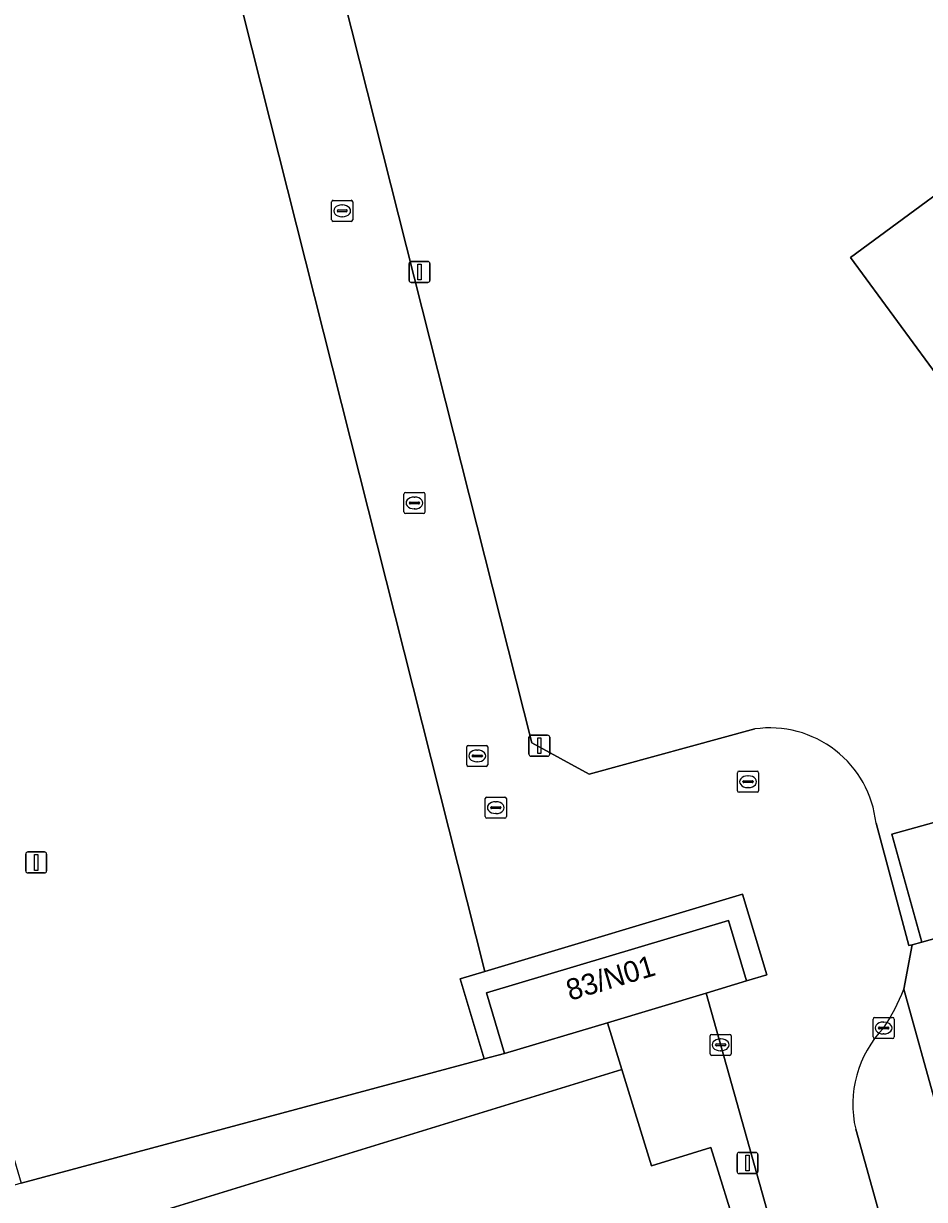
# Model space of a CAD drawing. Extents: x 161798 to 162385, y 382315 to 382833.
# Drawn here: x 161899.7 to 161942.5, y 382389.5 to 382445.3 of the extents above; entities that cross this region are included whole.
import ezdxf

# ---------------------------------------------------------------- set-up
doc = ezdxf.new("R2010")
doc.units = 0
for name, color, linetype in [('IMGEO_Erf', 7, 'Continuous'), ('IMGEO_Kolk', 7, 'Continuous'), ('IMGEO_Lichtmast', 7, 'Continuous'), ('IMGEO_Pand', 7, 'Continuous'), ('IMGEO_Pand_nummerreeks', 7, 'Continuous'), ('IMGEO_Parkeervlak_open', 7, 'Continuous'), ('IMGEO_Rijbaan_lokaal_open', 7, 'Continuous'), ('IMGEO_Rioolput', 7, 'Continuous'), ('IMGEO_Voetpad_open', 7, 'Continuous')]:
    doc.layers.add(name, color=color, linetype=linetype)

msp = doc.modelspace()

# ---------------------------------------------------------------- linework, layer by layer
at = {"layer": 'IMGEO_Erf'}
for points in [[(161943.046, 382494.363), (161935.085, 382489.806), (161935.055, 382489.789), (161936.244, 382487.804), (161938.108, 382484.585), (161938.514, 382483.884), (161935.731, 382482.274), (161935.489, 382482.679), (161932.899, 382481.486), (161935.813, 382475.159), (161932.857, 382473.767), (161932.015, 382475.589), (161928.142, 382473.799), (161924.693, 382472.205), (161925.53, 382470.395), (161922.269, 382468.888), (161918.832, 382467.419), (161919.424, 382465.747), (161910.817, 382462.697), (161923.855, 382411.141), (161926.575, 382409.655), (161934.439, 382411.796)], [(161944.197, 382427.091), (161938.983, 382434.18), (161953.966, 382445.201)], [(161940.197, 382407.325), (161941.76, 382401.512), (161941.909, 382401.548), (161942.37, 382401.676), (161940.944, 382406.8), (161949.609, 382409.212)]]:
    msp.add_lwpolyline(points, dxfattribs=at)
msp.add_arc((161935.153, 382406.772), 5.074, 6.2564, 98.086, dxfattribs=at)
at = {"layer": 'IMGEO_Kolk'}
for p, q in [((161914.341, 382435.967), (161914.341, 382436.819)), ((161914.416, 382436.893), (161915.268, 382436.893)), ((161915.342, 382436.819), (161915.342, 382435.967)), ((161914.6, 382436.387), (161914.6, 382436.399)), ((161915.038, 382436.35), (161914.64, 382436.35)), ((161914.643, 382436.436), (161915.041, 382436.436)), ((161914.829, 382436.673), (161914.854, 382436.673)), ((161915.084, 382436.399), (161915.084, 382436.387)), ((161915.268, 382435.893), (161914.416, 382435.893)), ((161914.852, 382436.113), (161914.827, 382436.113)), ((161917.773, 382422.099), (161917.773, 382422.951)), ((161917.848, 382423.025), (161918.7, 382423.025)), ((161918.261, 382422.805), (161918.286, 382422.805)), ((161918.774, 382422.951), (161918.774, 382422.099)), ((161918.032, 382422.519), (161918.032, 382422.531)), ((161918.47, 382422.482), (161918.072, 382422.482)), ((161918.075, 382422.568), (161918.473, 382422.568)), ((161918.284, 382422.245), (161918.259, 382422.245)), ((161918.516, 382422.531), (161918.516, 382422.519)), ((161918.7, 382422.025), (161917.848, 382422.025)), ((161920.755, 382410.091), (161920.755, 382410.943)), ((161920.83, 382411.017), (161921.682, 382411.017)), ((161921.014, 382410.511), (161921.014, 382410.523)), ((161921.057, 382410.56), (161921.455, 382410.56)), ((161921.243, 382410.797), (161921.268, 382410.797)), ((161921.498, 382410.523), (161921.498, 382410.511)), ((161921.756, 382410.943), (161921.756, 382410.091)), ((161921.682, 382410.017), (161920.83, 382410.017)), ((161921.452, 382410.474), (161921.054, 382410.474)), ((161921.266, 382410.237), (161921.241, 382410.237)), ((161933.616, 382408.865), (161933.616, 382409.717)), ((161933.691, 382409.791), (161934.543, 382409.791)), ((161934.104, 382409.571), (161934.129, 382409.571)), ((161934.617, 382409.717), (161934.617, 382408.865)), ((161933.875, 382409.285), (161933.875, 382409.297)), ((161934.313, 382409.248), (161933.915, 382409.248)), ((161933.918, 382409.334), (161934.316, 382409.334)), ((161934.127, 382409.011), (161934.102, 382409.011)), ((161934.359, 382409.297), (161934.359, 382409.285)), ((161934.543, 382408.791), (161933.691, 382408.791)), ((161940.056, 382397.172), (161940.056, 382398.024)), ((161940.131, 382398.098), (161940.983, 382398.098)), ((161940.544, 382397.878), (161940.569, 382397.878)), ((161941.057, 382398.024), (161941.057, 382397.172)), ((161932.316, 382396.372), (161932.316, 382397.224)), ((161932.391, 382397.298), (161933.243, 382397.298)), ((161933.317, 382397.224), (161933.317, 382396.372)), ((161940.983, 382397.098), (161940.131, 382397.098)), ((161940.315, 382397.592), (161940.315, 382397.604)), ((161940.753, 382397.555), (161940.355, 382397.555)), ((161940.358, 382397.641), (161940.756, 382397.641)), ((161940.567, 382397.318), (161940.542, 382397.318)), ((161940.799, 382397.604), (161940.799, 382397.592)), ((161932.575, 382396.792), (161932.575, 382396.804)), ((161933.013, 382396.755), (161932.615, 382396.755)), ((161932.618, 382396.841), (161933.016, 382396.841)), ((161932.804, 382397.078), (161932.829, 382397.078)), ((161933.059, 382396.804), (161933.059, 382396.792)), ((161933.243, 382396.298), (161932.391, 382396.298)), ((161932.827, 382396.518), (161932.802, 382396.518))]:
    msp.add_line(p, q, dxfattribs=at)
for points in [[(161914.341, 382435.967), (161914.341, 382436.819)], [(161914.416, 382436.893), (161915.268, 382436.893)], [(161915.342, 382436.819), (161915.342, 382435.967)], [(161915.268, 382435.893), (161914.416, 382435.893)], [(161917.773, 382422.099), (161917.773, 382422.951)], [(161917.848, 382423.025), (161918.7, 382423.025)], [(161918.774, 382422.951), (161918.774, 382422.099)], [(161918.7, 382422.025), (161917.848, 382422.025)], [(161920.755, 382410.091), (161920.755, 382410.943)], [(161920.83, 382411.017), (161921.682, 382411.017)], [(161921.756, 382410.943), (161921.756, 382410.091)], [(161921.682, 382410.017), (161920.83, 382410.017)], [(161933.616, 382408.865), (161933.616, 382409.717)], [(161933.691, 382409.791), (161934.543, 382409.791)], [(161934.617, 382409.717), (161934.617, 382408.865)], [(161934.543, 382408.791), (161933.691, 382408.791)], [(161940.056, 382397.172), (161940.056, 382398.024)], [(161940.131, 382398.098), (161940.983, 382398.098)], [(161941.057, 382398.024), (161941.057, 382397.172)], [(161932.316, 382396.372), (161932.316, 382397.224)], [(161932.391, 382397.298), (161933.243, 382397.298)], [(161933.317, 382397.224), (161933.317, 382396.372)], [(161940.983, 382397.098), (161940.131, 382397.098)], [(161933.243, 382396.298), (161932.391, 382396.298)]]:
    msp.add_lwpolyline(points, dxfattribs=at)
for centre, radius, start, end in [((161914.418, 382436.817), 0.0765, 91.552, 178.448), ((161914.418, 382436.817), 0.0765, 91.552, 178.448), ((161915.266, 382436.817), 0.0765, 1.552, 88.448), ((161915.266, 382436.817), 0.0765, 1.552, 88.448), ((161914.64, 382436.396), 0.0403, 85.8775, 175.7526), ((161914.637, 382436.386), 0.0366, 178.938, 274.7102), ((161915.041, 382436.393), 0.043, 264.8664, 352.4533), ((161915.045, 382436.398), 0.0386, 1.7309, 96.639), ((161914.418, 382435.969), 0.0765, 181.552, 268.448), ((161914.418, 382435.969), 0.0765, 181.552, 268.448), ((161915.266, 382435.969), 0.0765, 271.552, 358.448), ((161915.266, 382435.969), 0.0765, 271.552, 358.448), ((161917.85, 382422.949), 0.0765, 91.552, 178.448), ((161917.85, 382422.949), 0.0765, 91.552, 178.448), ((161918.698, 382422.949), 0.0765, 1.552, 88.448), ((161918.698, 382422.949), 0.0765, 1.552, 88.448), ((161918.072, 382422.528), 0.0403, 85.8775, 175.7526), ((161918.069, 382422.518), 0.0366, 178.938, 274.7102), ((161918.473, 382422.525), 0.043, 264.8664, 352.4533), ((161918.477, 382422.53), 0.0386, 1.7309, 96.639), ((161917.85, 382422.101), 0.0765, 181.552, 268.448), ((161917.85, 382422.101), 0.0765, 181.552, 268.448), ((161918.698, 382422.101), 0.0765, 271.552, 358.448), ((161918.698, 382422.101), 0.0765, 271.552, 358.448), ((161920.832, 382410.941), 0.0765, 91.552, 178.448), ((161920.832, 382410.941), 0.0765, 91.552, 178.448), ((161921.054, 382410.52), 0.0403, 85.8775, 175.7526), ((161921.051, 382410.51), 0.0366, 178.938, 274.7102), ((161921.455, 382410.517), 0.043, 264.8664, 352.4533), ((161921.459, 382410.522), 0.0386, 1.7309, 96.639), ((161921.68, 382410.941), 0.0765, 1.552, 88.448), ((161921.68, 382410.941), 0.0765, 1.552, 88.448), ((161920.832, 382410.093), 0.0765, 181.552, 268.448), ((161920.832, 382410.093), 0.0765, 181.552, 268.448), ((161921.68, 382410.093), 0.0765, 271.552, 358.448), ((161921.68, 382410.093), 0.0765, 271.552, 358.448), ((161933.693, 382409.715), 0.0765, 91.552, 178.448), ((161933.693, 382409.715), 0.0765, 91.552, 178.448), ((161934.541, 382409.715), 0.0765, 1.552, 88.448), ((161934.541, 382409.715), 0.0765, 1.552, 88.448), ((161933.693, 382408.867), 0.0765, 181.552, 268.448), ((161933.693, 382408.867), 0.0765, 181.552, 268.448), ((161933.915, 382409.294), 0.0403, 85.8775, 175.7526), ((161933.912, 382409.284), 0.0366, 178.938, 274.7102), ((161934.316, 382409.291), 0.043, 264.8664, 352.4533), ((161934.32, 382409.296), 0.0386, 1.7309, 96.639), ((161934.541, 382408.867), 0.0765, 271.552, 358.448), ((161934.541, 382408.867), 0.0765, 271.552, 358.448), ((161940.133, 382398.022), 0.0765, 91.552, 178.448), ((161940.133, 382398.022), 0.0765, 91.552, 178.448), ((161940.981, 382398.022), 0.0765, 1.552, 88.448), ((161940.981, 382398.022), 0.0765, 1.552, 88.448), ((161932.393, 382397.222), 0.0765, 91.552, 178.448), ((161932.393, 382397.222), 0.0765, 91.552, 178.448), ((161933.241, 382397.222), 0.0765, 1.552, 88.448), ((161933.241, 382397.222), 0.0765, 1.552, 88.448), ((161940.133, 382397.174), 0.0765, 181.552, 268.448), ((161940.133, 382397.174), 0.0765, 181.552, 268.448), ((161940.355, 382397.601), 0.0403, 85.8775, 175.7526), ((161940.352, 382397.591), 0.0366, 178.938, 274.7102), ((161940.756, 382397.598), 0.043, 264.8664, 352.4533), ((161940.76, 382397.603), 0.0386, 1.7309, 96.639), ((161940.981, 382397.174), 0.0765, 271.552, 358.448), ((161940.981, 382397.174), 0.0765, 271.552, 358.448), ((161932.615, 382396.801), 0.0403, 85.8775, 175.7526), ((161932.612, 382396.791), 0.0366, 178.938, 274.7102), ((161933.016, 382396.798), 0.043, 264.8664, 352.4533), ((161933.02, 382396.803), 0.0386, 1.7309, 96.639), ((161932.393, 382396.374), 0.0765, 181.552, 268.448), ((161932.393, 382396.374), 0.0765, 181.552, 268.448), ((161933.241, 382396.374), 0.0765, 271.552, 358.448), ((161933.241, 382396.374), 0.0765, 271.552, 358.448)]:
    msp.add_arc(centre, radius, start, end, dxfattribs=at)
for centre, major_axis, ratio, start_param, end_param in [((161914.828, 382436.393), (-0.387, 0.002), 0.722429, 4.712389, 7.853982), ((161914.853, 382436.393), (-0.39, 0.002), 0.717154, 1.570796, 4.712389), ((161918.26, 382422.525), (-0.387, 0.002), 0.722429, 4.712389, 7.853982), ((161918.285, 382422.525), (-0.39, 0.002), 0.717154, 1.570796, 4.712389), ((161921.242, 382410.517), (-0.387, 0.002), 0.722429, 4.712389, 7.853982), ((161921.267, 382410.517), (-0.39, 0.002), 0.717154, 1.570796, 4.712389), ((161934.103, 382409.291), (-0.387, 0.002), 0.722429, 4.712389, 7.853982), ((161934.128, 382409.291), (-0.39, 0.002), 0.717154, 1.570796, 4.712389), ((161940.543, 382397.598), (-0.387, 0.002), 0.722429, 4.712389, 7.853982), ((161940.568, 382397.598), (-0.39, 0.002), 0.717154, 1.570796, 4.712389), ((161932.803, 382396.798), (-0.387, 0.002), 0.722429, 4.712389, 7.853982), ((161932.828, 382396.798), (-0.39, 0.002), 0.717154, 1.570796, 4.712389)]:
    msp.add_ellipse(centre, major_axis=major_axis, ratio=ratio, start_param=start_param, end_param=end_param, dxfattribs=at)
at = {"layer": 'IMGEO_Lichtmast'}
for p, q in [((161918.118, 382433.993), (161918.908, 382433.993)), ((161918.908, 382433.993), (161918.118, 382433.993)), ((161918.018, 382433.093), (161918.018, 382433.893)), ((161918.018, 382433.893), (161918.018, 382433.093)), ((161919.008, 382433.893), (161919.008, 382433.093)), ((161919.008, 382433.093), (161919.008, 382433.893)), ((161918.908, 382432.993), (161918.118, 382432.993)), ((161918.118, 382432.993), (161918.908, 382432.993)), ((161923.706, 382410.601), (161923.706, 382411.401)), ((161923.706, 382411.401), (161923.706, 382410.601)), ((161923.806, 382411.501), (161924.596, 382411.501)), ((161924.596, 382411.501), (161923.806, 382411.501)), ((161924.696, 382411.401), (161924.696, 382410.601)), ((161924.696, 382410.601), (161924.696, 382411.401)), ((161924.596, 382410.501), (161923.806, 382410.501)), ((161923.806, 382410.501), (161924.596, 382410.501)), ((161899.813, 382405.059), (161899.813, 382405.859)), ((161899.813, 382405.859), (161899.813, 382405.059)), ((161899.913, 382405.959), (161900.703, 382405.959)), ((161900.703, 382405.959), (161899.913, 382405.959)), ((161900.803, 382405.859), (161900.803, 382405.059)), ((161900.803, 382405.059), (161900.803, 382405.859)), ((161900.703, 382404.959), (161899.913, 382404.959)), ((161899.913, 382404.959), (161900.703, 382404.959)), ((161933.594, 382390.791), (161933.594, 382391.591)), ((161933.594, 382391.591), (161933.594, 382390.791)), ((161933.694, 382391.691), (161934.484, 382391.691)), ((161934.484, 382391.691), (161933.694, 382391.691)), ((161934.584, 382391.591), (161934.584, 382390.791)), ((161934.584, 382390.791), (161934.584, 382391.591)), ((161934.484, 382390.691), (161933.694, 382390.691)), ((161933.694, 382390.691), (161934.484, 382390.691))]:
    msp.add_line(p, q, dxfattribs=at)
for points in [[(161918.438, 382433.868), (161918.588, 382433.868), (161918.588, 382433.118), (161918.438, 382433.118), (161918.438, 382433.868)], [(161924.126, 382411.376), (161924.276, 382411.376), (161924.276, 382410.626), (161924.126, 382410.626), (161924.126, 382411.376)], [(161900.233, 382405.834), (161900.383, 382405.834), (161900.383, 382405.084), (161900.233, 382405.084), (161900.233, 382405.834)], [(161934.014, 382391.566), (161934.164, 382391.566), (161934.164, 382390.816), (161934.014, 382390.816), (161934.014, 382391.566)]]:
    msp.add_lwpolyline(points, dxfattribs=at)
for centre, start, end in [((161918.118, 382433.893), 90, 180), ((161918.118, 382433.893), 90, 180), ((161918.908, 382433.893), 0, 90), ((161918.908, 382433.893), 360, 90), ((161918.118, 382433.093), 180, 270), ((161918.118, 382433.093), 180, 270), ((161918.908, 382433.093), 270, 0), ((161918.908, 382433.093), 270, 0), ((161923.806, 382411.401), 90, 180), ((161923.806, 382411.401), 90, 180), ((161924.596, 382411.401), 0, 90), ((161924.596, 382411.401), 360, 90), ((161923.806, 382410.601), 180, 270), ((161923.806, 382410.601), 180, 270), ((161924.596, 382410.601), 270, 0), ((161924.596, 382410.601), 270, 0), ((161899.913, 382405.859), 90, 180), ((161899.913, 382405.859), 90, 180), ((161900.703, 382405.859), 0, 90), ((161900.703, 382405.859), 360, 90), ((161899.913, 382405.059), 180, 270), ((161899.913, 382405.059), 180, 270), ((161900.703, 382405.059), 270, 0), ((161900.703, 382405.059), 270, 0), ((161933.694, 382391.591), 90, 180), ((161933.694, 382391.591), 90, 180), ((161934.484, 382391.591), 0, 90), ((161934.484, 382391.591), 360, 90), ((161933.694, 382390.791), 180, 270), ((161933.694, 382390.791), 180, 270), ((161934.484, 382390.791), 270, 0), ((161934.484, 382390.791), 270, 0)]:
    msp.add_arc(centre, 0.1, start, end, dxfattribs=at)
at = {"layer": 'IMGEO_Pand'}
for points in [[(161953.966, 382445.201), (161938.983, 382434.18), (161944.197, 382427.091)], [(161933.661, 382387.68), (161932.357, 382391.919), (161929.53, 382391.05), (161928.121, 382395.631), (161889.82, 382383.852)]]:
    msp.add_lwpolyline(points, dxfattribs=at)
for points in [[(161973.948, 382413.567), (161951.23, 382407.316), (161951.302, 382407.048), (161952.02, 382404.363), (161942.37, 382401.676), (161941.909, 382401.548), (161941.516, 382399.444), (161943.116, 382393.678), (161980.926, 382404.082)], [(161951.302, 382407.048), (161949.609, 382409.212), (161940.944, 382406.8), (161942.37, 382401.676), (161952.02, 382404.363)], [(161932.127, 382399.256), (161934.047, 382399.831), (161933.186, 382402.705), (161921.692, 382399.261), (161922.553, 382396.388), (161927.439, 382397.852)]]:
    msp.add_lwpolyline(points, close=True, dxfattribs=at)
at = {"layer": 'IMGEO_Parkeervlak_open'}
msp.add_lwpolyline([(161921.617, 382400.283), (161906.292, 382461), (161905.994, 382460.889), (161905.116, 382460.594), (161900.621, 382458.999), (161891.021, 382455.593), (161881.317, 382452.151), (161876.01, 382450.268), (161875.365, 382452.391), (161874.089, 382451.938), (161880.456, 382430.992), (161886.924, 382433.066), (161891.177, 382418.691), (161895.348, 382404.595), (161899.598, 382390.231), (161921.586, 382396.128), (161920.447, 382399.932)], close=True, dxfattribs=at)
msp.add_lwpolyline([(161939.23, 382392.79), (161942.76, 382380.116), (161944.182, 382380.534), (161971.566, 382388.238), (161988.977, 382393.137), (161980.926, 382404.082), (161943.116, 382393.678), (161941.516, 382399.444)], dxfattribs=at)
for centre, radius, start, end in [((161932.118, 382403.154), 10.104, 326.6397, 338.4564), ((161944.322, 382393.972), 5.228, 136.078, 193.0632)]:
    msp.add_arc(centre, radius, start, end, dxfattribs=at)
at = {"layer": 'IMGEO_Rijbaan_lokaal_open'}
for points in [[(161934.439, 382411.796), (161926.575, 382409.655), (161923.855, 382411.141), (161910.817, 382462.697), (161909.508, 382462.233), (161906.292, 382461), (161921.617, 382400.283), (161933.857, 382403.95), (161935.005, 382400.118), (161934.047, 382399.831), (161932.127, 382399.256), (161940.588, 382369.122), (161942.874, 382360.967), (161947.708, 382362.337), (161945.903, 382368.808), (161942.76, 382380.116), (161939.23, 382392.79)], [(161941.516, 382399.444), (161941.909, 382401.548), (161941.76, 382401.512), (161940.197, 382407.325)]]:
    msp.add_lwpolyline(points, dxfattribs=at)
for centre, radius, start, end in [((161935.153, 382406.772), 5.074, 6.2564, 98.086), ((161932.118, 382403.154), 10.104, 326.6397, 338.4564), ((161944.322, 382393.972), 5.228, 136.078, 193.0632)]:
    msp.add_arc(centre, radius, start, end, dxfattribs=at)
at = {"layer": 'IMGEO_Rioolput'}
for p, q in [((161921.637, 382407.635), (161921.637, 382408.487)), ((161921.712, 382408.561), (161922.564, 382408.561)), ((161922.125, 382408.341), (161922.15, 382408.341)), ((161922.638, 382408.487), (161922.638, 382407.635)), ((161921.896, 382408.055), (161921.896, 382408.067)), ((161922.334, 382408.018), (161921.936, 382408.018)), ((161921.939, 382408.104), (161922.337, 382408.104)), ((161922.148, 382407.781), (161922.123, 382407.781)), ((161922.38, 382408.067), (161922.38, 382408.055)), ((161922.564, 382407.561), (161921.712, 382407.561))]:
    msp.add_line(p, q, dxfattribs=at)
for points in [[(161921.637, 382407.635), (161921.637, 382408.487)], [(161921.712, 382408.561), (161922.564, 382408.561)], [(161922.638, 382408.487), (161922.638, 382407.635)], [(161922.564, 382407.561), (161921.712, 382407.561)]]:
    msp.add_lwpolyline(points, dxfattribs=at)
for centre, radius, start, end in [((161921.714, 382408.485), 0.0765, 91.552, 178.448), ((161921.714, 382408.485), 0.0765, 91.552, 178.448), ((161922.562, 382408.485), 0.0765, 1.552, 88.448), ((161922.562, 382408.485), 0.0765, 1.552, 88.448), ((161921.936, 382408.064), 0.0403, 85.8775, 175.7526), ((161921.933, 382408.054), 0.0366, 178.938, 274.7102), ((161922.337, 382408.061), 0.043, 264.8664, 352.4533), ((161922.341, 382408.066), 0.0386, 1.7309, 96.639), ((161921.714, 382407.637), 0.0765, 181.552, 268.448), ((161921.714, 382407.637), 0.0765, 181.552, 268.448), ((161922.562, 382407.637), 0.0765, 271.552, 358.448), ((161922.562, 382407.637), 0.0765, 271.552, 358.448)]:
    msp.add_arc(centre, radius, start, end, dxfattribs=at)
for centre, major_axis, ratio, start_param, end_param in [((161922.124, 382408.061), (-0.387, 0.002), 0.722429, 4.712389, 7.853982), ((161922.149, 382408.061), (-0.39, 0.002), 0.717154, 1.570796, 4.712389)]:
    msp.add_ellipse(centre, major_axis=major_axis, ratio=ratio, start_param=start_param, end_param=end_param, dxfattribs=at)
at = {"layer": 'IMGEO_Voetpad_open'}
for points in [[(161935.005, 382400.118), (161933.857, 382403.95), (161921.617, 382400.283), (161920.447, 382399.932), (161921.586, 382396.128), (161922.553, 382396.388), (161921.692, 382399.261), (161933.186, 382402.705), (161934.047, 382399.831)], [(161922.553, 382396.388), (161921.586, 382396.128), (161899.598, 382390.231), (161888.821, 382387.042), (161889.82, 382383.852), (161928.121, 382395.631), (161927.439, 382397.852)]]:
    msp.add_lwpolyline(points, close=True, dxfattribs=at)
msp.add_lwpolyline([(161949.893, 382362.105), (161949.687, 382362.852), (161949.205, 382362.714), (161947.708, 382362.337), (161942.874, 382360.967), (161940.588, 382369.122), (161932.127, 382399.256), (161927.439, 382397.852), (161928.121, 382395.631), (161929.53, 382391.05), (161932.357, 382391.919), (161933.661, 382387.68), (161934.42, 382387.913), (161939.328, 382371.953), (161898.08, 382359.268), (161891.002, 382357.853), (161892.935, 382352.175)], dxfattribs=at)

# ---------------------------------------------------------------- texts
at = {"layer": 'IMGEO_Pand_nummerreeks'}
msp.add_text('83/N01', height=1, rotation=16.6723, dxfattribs=at).set_placement((161925.663, 382398.886))

doc.saveas('drawing.dxf')
